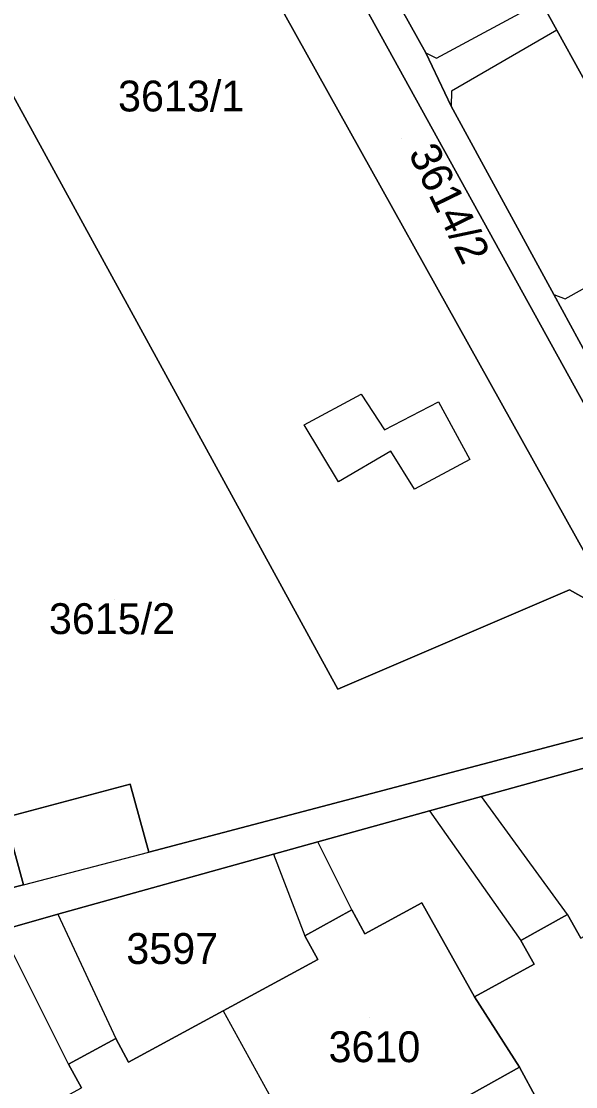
# Model space of a CAD drawing. Extents: x -262715 to -259381, y -1237238 to -1231182.
# Drawn here: x -261657.7 to -261621.8, y -1236094.5 to -1236025.5 of the extents above; entities that cross this region are included whole.
import ezdxf

# ---------------------------------------------------------------- set-up
doc = ezdxf.new("R2010")
doc.units = 0
for name, color, linetype in [('body_kn', 7, 'Continuous'), ('kladpar_druhypozemkov', 7, 'Continuous'), ('kladpar_hranice', 7, 'Continuous'), ('kladpar_parcelnecisla', 7, 'Continuous'), ('kladpar_plochy', 7, 'Continuous'), ('zappar_hrandruhpozemk', 7, 'Continuous')]:
    doc.layers.add(name, color=color, linetype=linetype)

msp = doc.modelspace()

# ---------------------------------------------------------------- linework, layer by layer
at = {"layer": 'body_kn'}
for p, q in [((-261622.99, -1236026.04), (-261622.99, -1236026.04)), ((-261622.99, -1236026.04), (-261622.99, -1236026.04)), ((-261631.49, -1236027.51), (-261631.49, -1236027.51)), ((-261631.49, -1236027.51), (-261631.49, -1236027.51)), ((-261630.8, -1236027.86), (-261630.8, -1236027.86)), ((-261629.82, -1236029.99), (-261629.82, -1236029.99)), ((-261629.83, -1236030.97), (-261629.83, -1236030.97)), ((-261623.18, -1236043.17), (-261623.18, -1236043.17)), ((-261623.18, -1236043.17), (-261623.18, -1236043.17)), ((-261622.46, -1236043.47), (-261622.46, -1236043.47)), ((-261635.68, -1236049.65), (-261635.68, -1236049.65)), ((-261635.68, -1236049.65), (-261635.68, -1236049.65)), ((-261630.67, -1236050.14), (-261630.67, -1236050.14)), ((-261639.36, -1236051.63), (-261639.36, -1236051.63)), ((-261634.15, -1236051.96), (-261634.15, -1236051.96)), ((-261633.75, -1236053.33), (-261633.75, -1236053.33)), ((-261628.64, -1236053.89), (-261628.64, -1236053.89)), ((-261637.15, -1236055.33), (-261637.15, -1236055.33)), ((-261632.21, -1236055.81), (-261632.21, -1236055.81)), ((-261622.18, -1236062.34), (-261622.18, -1236062.34)), ((-261637.19, -1236068.77), (-261637.19, -1236068.77)), ((-261650.64, -1236074.94), (-261650.64, -1236074.94)), ((-261627.87, -1236075.74), (-261627.87, -1236075.74)), ((-261631.24, -1236076.67), (-261631.24, -1236076.67)), ((-261631.24, -1236076.67), (-261631.24, -1236076.67)), ((-261638.47, -1236078.68), (-261638.47, -1236078.68)), ((-261649.43, -1236079.35), (-261649.43, -1236079.35)), ((-261641.36, -1236079.48), (-261641.36, -1236079.48)), ((-261641.36, -1236079.48), (-261641.36, -1236079.48)), ((-261657.56, -1236081.47), (-261657.56, -1236081.47)), ((-261657.56, -1236081.47), (-261657.56, -1236081.47)), ((-261631.74, -1236082.62), (-261631.74, -1236082.62)), ((-261631.74, -1236082.62), (-261631.74, -1236082.62)), ((-261636.28, -1236083.09), (-261636.28, -1236083.09)), ((-261636.28, -1236083.09), (-261636.28, -1236083.09)), ((-261655.33, -1236083.36), (-261655.33, -1236083.36)), ((-261655.33, -1236083.36), (-261655.33, -1236083.36)), ((-261622.3, -1236083.38), (-261622.3, -1236083.38)), ((-261622.3, -1236083.38), (-261622.3, -1236083.38)), ((-261635.44, -1236084.63), (-261635.44, -1236084.63)), ((-261639.33, -1236084.76), (-261639.33, -1236084.76)), ((-261625.32, -1236085.07), (-261625.32, -1236085.07)), ((-261638.49, -1236086.3), (-261638.49, -1236086.3)), ((-261624.45, -1236086.61), (-261624.45, -1236086.61)), ((-261628.33, -1236088.72), (-261628.33, -1236088.72)), ((-261644.61, -1236089.63), (-261644.61, -1236089.63)), ((-261644.61, -1236089.63), (-261644.61, -1236089.63)), ((-261651.58, -1236091.43), (-261651.58, -1236091.43)), ((-261650.74, -1236092.97), (-261650.74, -1236092.97)), ((-261654.63, -1236093.09), (-261654.63, -1236093.09)), ((-261654.63, -1236093.09), (-261654.63, -1236093.09)), ((-261625.42, -1236093.29), (-261625.42, -1236093.29))]:
    msp.add_line(p, q, dxfattribs=at)
at = {"layer": 'kladpar_druhypozemkov'}
for p, q in [((-261648.04, -1236029.31), (-261648.04, -1236029.31)), ((-261633.04, -1236033.09), (-261633.04, -1236033.09)), ((-261651.67, -1236062.97), (-261651.67, -1236062.97)), ((-261647.98, -1236085.05), (-261647.98, -1236085.05)), ((-261635.11, -1236090.07), (-261635.11, -1236090.07))]:
    msp.add_line(p, q, dxfattribs=at)
at = {"layer": 'kladpar_hranice'}
for points in [[(-261659.37, -1235991.22), (-261659.15, -1235991.62), (-261645.89, -1236015.37), (-261641.6, -1236013.13), (-261640.57, -1236015.16), (-261644.84, -1236017.45), (-261620.32, -1236061.49), (-261612.68, -1236065.74), (-261611.06, -1236068.53), (-261622.18, -1236062.34), (-261637.19, -1236068.77), (-261660.5, -1236026.2), (-261662.24, -1236030.9), (-261668.09, -1236046.76), (-261669.85, -1236046.53), (-261663.82, -1236030.1), (-261661.6, -1236024.18), (-261675.14, -1235999.74), (-261672.65, -1235998.38), (-261670.9, -1235997.38), (-261659.61, -1235991.35), (-261659.37, -1235991.22)], [(-261660.79, -1236082.28), (-261657.56, -1236081.47), (-261658.74, -1236077.09), (-261650.64, -1236074.94), (-261649.43, -1236079.35), (-261611.8, -1236069.42), (-261611.21, -1236069.04), (-261611.06, -1236068.53), (-261612.68, -1236065.74), (-261640.57, -1236015.16), (-261641.6, -1236013.13), (-261650.52, -1235996.67)], [(-261647.9, -1235998.2), (-261646.63, -1236000.41), (-261640.68, -1236011.22), (-261638.32, -1236015.22), (-261631.49, -1236027.51), (-261629.83, -1236030.97), (-261623.18, -1236043.17), (-261621.56, -1236046.17), (-261615.02, -1236058.24), (-261613.26, -1236061.42), (-261610.77, -1236066.07), (-261610.24, -1236066.68), (-261609.28, -1236067), (-261603.31, -1236063.61), (-261601.54, -1236066.77), (-261603.15, -1236067.76), (-261610.52, -1236070.92), (-261613.9, -1236071.86), (-261627.87, -1236075.74), (-261631.24, -1236076.67), (-261638.47, -1236078.68), (-261641.36, -1236079.48), (-261655.33, -1236083.36), (-261660.25, -1236084.77)], [(-261640.57, -1236015.16), (-261612.68, -1236065.74), (-261620.32, -1236061.49), (-261644.84, -1236017.45), (-261640.57, -1236015.16)], [(-261624, -1236024.2), (-261622.99, -1236026.04), (-261619.83, -1236031.75), (-261615.51, -1236039.55), (-261614.55, -1236041.3), (-261611.4, -1236047), (-261607.15, -1236054.68), (-261606.11, -1236056.56), (-261602.75, -1236062.64), (-261603.6, -1236063.1), (-261603.31, -1236063.61), (-261609.28, -1236067), (-261610.24, -1236066.68), (-261610.77, -1236066.07), (-261613.26, -1236061.42), (-261615.02, -1236058.24), (-261621.56, -1236046.17), (-261623.18, -1236043.17), (-261629.83, -1236030.97), (-261631.49, -1236027.51), (-261638.32, -1236015.22)], [(-261612.21, -1236019.61), (-261608.94, -1236025.55), (-261605.64, -1236031.53), (-261603.51, -1236030.36), (-261601.67, -1236033.71), (-261603.79, -1236034.88), (-261600.53, -1236040.81), (-261597.23, -1236046.8), (-261595.12, -1236045.63), (-261593.28, -1236048.96), (-261595.39, -1236050.12), (-261591.96, -1236056.36), (-261593.48, -1236057.24), (-261602.75, -1236062.64), (-261606.11, -1236056.56), (-261607.15, -1236054.68), (-261611.4, -1236047), (-261614.55, -1236041.3), (-261615.51, -1236039.55), (-261619.83, -1236031.75), (-261622.99, -1236026.04), (-261624, -1236024.2)], [(-261660.5, -1236026.2), (-261637.19, -1236068.77), (-261622.18, -1236062.34), (-261611.06, -1236068.53), (-261611.21, -1236069.04), (-261611.8, -1236069.42), (-261649.43, -1236079.35), (-261650.64, -1236074.94), (-261658.74, -1236077.09), (-261657.56, -1236081.47), (-261660.79, -1236082.28), (-261665.52, -1236083.61), (-261670.57, -1236062.39), (-261664.06, -1236058.99), (-261665.52, -1236056.54), (-261670.41, -1236058.93), (-261668.24, -1236055.62), (-261664.95, -1236053.14), (-261668.09, -1236046.76), (-261662.24, -1236030.9), (-261660.5, -1236026.2)], [(-261660.25, -1236084.77), (-261655.33, -1236083.36), (-261641.36, -1236079.48), (-261638.47, -1236078.68), (-261631.24, -1236076.67), (-261627.87, -1236075.74), (-261613.9, -1236071.86)], [(-261602.6, -1236074.32), (-261597.99, -1236082.53), (-261596.41, -1236085.34), (-261601, -1236087.9), (-261603.17, -1236089.12), (-261608.83, -1236092.29), (-261615.44, -1236095.98), (-261617.45, -1236097.11), (-261621.98, -1236099.64), (-261625.42, -1236093.29), (-261628.33, -1236088.72), (-261624.45, -1236086.61), (-261625.32, -1236085.07), (-261622.3, -1236083.38), (-261621.44, -1236084.91), (-261615.24, -1236081.42), (-261609.28, -1236078.07), (-261610.14, -1236076.56), (-261607.12, -1236074.88), (-261606.28, -1236076.38), (-261602.6, -1236074.32)], [(-261631.74, -1236082.62), (-261628.33, -1236088.72), (-261625.42, -1236093.29), (-261630.02, -1236095.86), (-261632.07, -1236097), (-261638.57, -1236100.63), (-261645.12, -1236104.28), (-261647.09, -1236105.38), (-261651.38, -1236107.78), (-261657.48, -1236096.64), (-261653.79, -1236094.63), (-261654.63, -1236093.09), (-261651.58, -1236091.43), (-261650.74, -1236092.97), (-261644.61, -1236089.63), (-261638.49, -1236086.3), (-261639.33, -1236084.76), (-261636.28, -1236083.09), (-261635.44, -1236084.63), (-261631.74, -1236082.62)], [(-261621.44, -1236084.91), (-261622.3, -1236083.38), (-261625.32, -1236085.07), (-261624.45, -1236086.61), (-261628.33, -1236088.72), (-261631.74, -1236082.62), (-261635.44, -1236084.63), (-261636.28, -1236083.09), (-261639.33, -1236084.76), (-261638.49, -1236086.3), (-261644.61, -1236089.63), (-261650.74, -1236092.97), (-261651.58, -1236091.43), (-261654.63, -1236093.09), (-261653.79, -1236094.63)], [(-261630.02, -1236095.86), (-261625.42, -1236093.29), (-261621.98, -1236099.64)]]:
    msp.add_lwpolyline(points, dxfattribs=at)
at = {"layer": 'kladpar_plochy'}
for points in [[(-261659.37, -1235991.22), (-261659.15, -1235991.62), (-261645.89, -1236015.37), (-261641.6, -1236013.13), (-261640.57, -1236015.16), (-261644.84, -1236017.45), (-261620.32, -1236061.49), (-261612.68, -1236065.74), (-261611.06, -1236068.53), (-261622.18, -1236062.34), (-261637.19, -1236068.77), (-261660.5, -1236026.2), (-261662.24, -1236030.9), (-261668.09, -1236046.76), (-261669.85, -1236046.53), (-261663.82, -1236030.1), (-261661.6, -1236024.18), (-261675.14, -1235999.74), (-261672.65, -1235998.38), (-261670.9, -1235997.38), (-261659.61, -1235991.35)], [(-261640.57, -1236015.16), (-261612.68, -1236065.74), (-261620.32, -1236061.49), (-261644.84, -1236017.45)], [(-261660.5, -1236026.2), (-261637.19, -1236068.77), (-261622.18, -1236062.34), (-261611.06, -1236068.53), (-261611.21, -1236069.04), (-261611.8, -1236069.42), (-261649.43, -1236079.35), (-261650.64, -1236074.94), (-261658.74, -1236077.09), (-261657.56, -1236081.47), (-261660.79, -1236082.28), (-261665.52, -1236083.61), (-261670.57, -1236062.39), (-261664.06, -1236058.99), (-261665.52, -1236056.54), (-261670.41, -1236058.93), (-261668.24, -1236055.62), (-261664.95, -1236053.14), (-261668.09, -1236046.76), (-261662.24, -1236030.9)], [(-261602.6, -1236074.32), (-261597.99, -1236082.53), (-261596.41, -1236085.34), (-261601, -1236087.9), (-261603.17, -1236089.12), (-261608.83, -1236092.29), (-261615.44, -1236095.98), (-261617.45, -1236097.11), (-261621.98, -1236099.64), (-261625.42, -1236093.29), (-261628.33, -1236088.72), (-261624.45, -1236086.61), (-261625.32, -1236085.07), (-261622.3, -1236083.38), (-261621.44, -1236084.91), (-261615.24, -1236081.42), (-261609.28, -1236078.07), (-261610.14, -1236076.56), (-261607.12, -1236074.88), (-261606.28, -1236076.38)], [(-261631.74, -1236082.62), (-261628.33, -1236088.72), (-261625.42, -1236093.29), (-261630.02, -1236095.86), (-261632.07, -1236097), (-261638.57, -1236100.63), (-261645.12, -1236104.28), (-261647.09, -1236105.38), (-261651.38, -1236107.78), (-261657.48, -1236096.64), (-261653.79, -1236094.63), (-261654.63, -1236093.09), (-261651.58, -1236091.43), (-261650.74, -1236092.97), (-261644.61, -1236089.63), (-261638.49, -1236086.3), (-261639.33, -1236084.76), (-261636.28, -1236083.09), (-261635.44, -1236084.63)]]:
    msp.add_lwpolyline(points, close=True, dxfattribs=at)
for points in [[(-261660.79, -1236082.28), (-261657.56, -1236081.47), (-261658.74, -1236077.09), (-261650.64, -1236074.94), (-261649.43, -1236079.35), (-261611.8, -1236069.42), (-261611.21, -1236069.04), (-261611.06, -1236068.53), (-261612.68, -1236065.74), (-261640.57, -1236015.16)], [(-261638.32, -1236015.22), (-261631.49, -1236027.51), (-261629.83, -1236030.97), (-261623.18, -1236043.17), (-261621.56, -1236046.17), (-261615.02, -1236058.24), (-261613.26, -1236061.42), (-261610.77, -1236066.07), (-261610.24, -1236066.68), (-261609.28, -1236067), (-261603.31, -1236063.61), (-261601.54, -1236066.77), (-261603.15, -1236067.76), (-261610.52, -1236070.92), (-261613.9, -1236071.86), (-261627.87, -1236075.74), (-261631.24, -1236076.67), (-261638.47, -1236078.68), (-261641.36, -1236079.48), (-261655.33, -1236083.36), (-261660.25, -1236084.77)], [(-261624, -1236024.2), (-261622.99, -1236026.04), (-261619.83, -1236031.75), (-261615.51, -1236039.55), (-261614.55, -1236041.3), (-261611.4, -1236047), (-261607.15, -1236054.68), (-261606.11, -1236056.56), (-261602.75, -1236062.64), (-261603.6, -1236063.1), (-261603.31, -1236063.61), (-261609.28, -1236067), (-261610.24, -1236066.68), (-261610.77, -1236066.07), (-261613.26, -1236061.42), (-261615.02, -1236058.24), (-261621.56, -1236046.17), (-261623.18, -1236043.17), (-261629.83, -1236030.97), (-261631.49, -1236027.51), (-261638.32, -1236015.22)], [(-261612.21, -1236019.61), (-261608.94, -1236025.55), (-261605.64, -1236031.53), (-261603.51, -1236030.36), (-261601.67, -1236033.71), (-261603.79, -1236034.88), (-261600.53, -1236040.81), (-261597.23, -1236046.8), (-261595.12, -1236045.63), (-261593.28, -1236048.96), (-261595.39, -1236050.12), (-261591.96, -1236056.36), (-261593.48, -1236057.24), (-261602.75, -1236062.64), (-261606.11, -1236056.56), (-261607.15, -1236054.68), (-261611.4, -1236047), (-261614.55, -1236041.3), (-261615.51, -1236039.55), (-261619.83, -1236031.75), (-261622.99, -1236026.04), (-261624, -1236024.2)], [(-261660.25, -1236084.77), (-261655.33, -1236083.36), (-261641.36, -1236079.48), (-261638.47, -1236078.68), (-261631.24, -1236076.67), (-261627.87, -1236075.74), (-261613.9, -1236071.86)], [(-261621.44, -1236084.91), (-261622.3, -1236083.38), (-261625.32, -1236085.07), (-261624.45, -1236086.61), (-261628.33, -1236088.72), (-261631.74, -1236082.62), (-261635.44, -1236084.63), (-261636.28, -1236083.09), (-261639.33, -1236084.76), (-261638.49, -1236086.3), (-261644.61, -1236089.63), (-261650.74, -1236092.97), (-261651.58, -1236091.43), (-261654.63, -1236093.09), (-261653.79, -1236094.63)], [(-261630.02, -1236095.86), (-261625.42, -1236093.29), (-261621.98, -1236099.64)]]:
    msp.add_lwpolyline(points, dxfattribs=at)
at = {"layer": 'zappar_hrandruhpozemk'}
for p, q in [((-261630.8, -1236027.86), (-261624, -1236024.2)), ((-261622.99, -1236026.04), (-261629.82, -1236029.99)), ((-261631.49, -1236027.51), (-261630.8, -1236027.86)), ((-261629.82, -1236029.99), (-261629.83, -1236030.97)), ((-261622.46, -1236043.47), (-261615.51, -1236039.55)), ((-261623.18, -1236043.17), (-261622.46, -1236043.47)), ((-261628.64, -1236053.89), (-261632.21, -1236055.81)), ((-261622.3, -1236083.38), (-261627.87, -1236075.74)), ((-261631.24, -1236076.67), (-261625.32, -1236085.07)), ((-261636.28, -1236083.09), (-261638.47, -1236078.68)), ((-261657.56, -1236081.47), (-261649.43, -1236079.35)), ((-261641.36, -1236079.48), (-261639.33, -1236084.76)), ((-261655.33, -1236083.36), (-261651.58, -1236091.43)), ((-261654.63, -1236093.09), (-261658.62, -1236085.14)), ((-261644.61, -1236089.63), (-261638.57, -1236100.63))]:
    msp.add_line(p, q, dxfattribs=at)
for points in [[(-261632.21, -1236055.81), (-261633.75, -1236053.33), (-261637.15, -1236055.33), (-261639.36, -1236051.63), (-261635.68, -1236049.65)], [(-261635.68, -1236049.65), (-261634.15, -1236051.96), (-261630.67, -1236050.14), (-261628.64, -1236053.89)]]:
    msp.add_lwpolyline(points, dxfattribs=at)

# ---------------------------------------------------------------- texts
at = {"layer": 'kladpar_parcelnecisla'}
for s, p in [('3613/1', (-261651.426, -1236031.31)), ('3615/2', (-261655.905, -1236065.2)), ('3597', (-261650.89, -1236086.59)), ('3610', (-261637.784, -1236092.96))]:
    msp.add_text(s, height=2, dxfattribs=at).set_placement(p)
msp.add_text('3614/2', height=2, rotation=296, dxfattribs=at).set_placement((-261632.638, -1236034.017))

doc.saveas('drawing.dxf')
